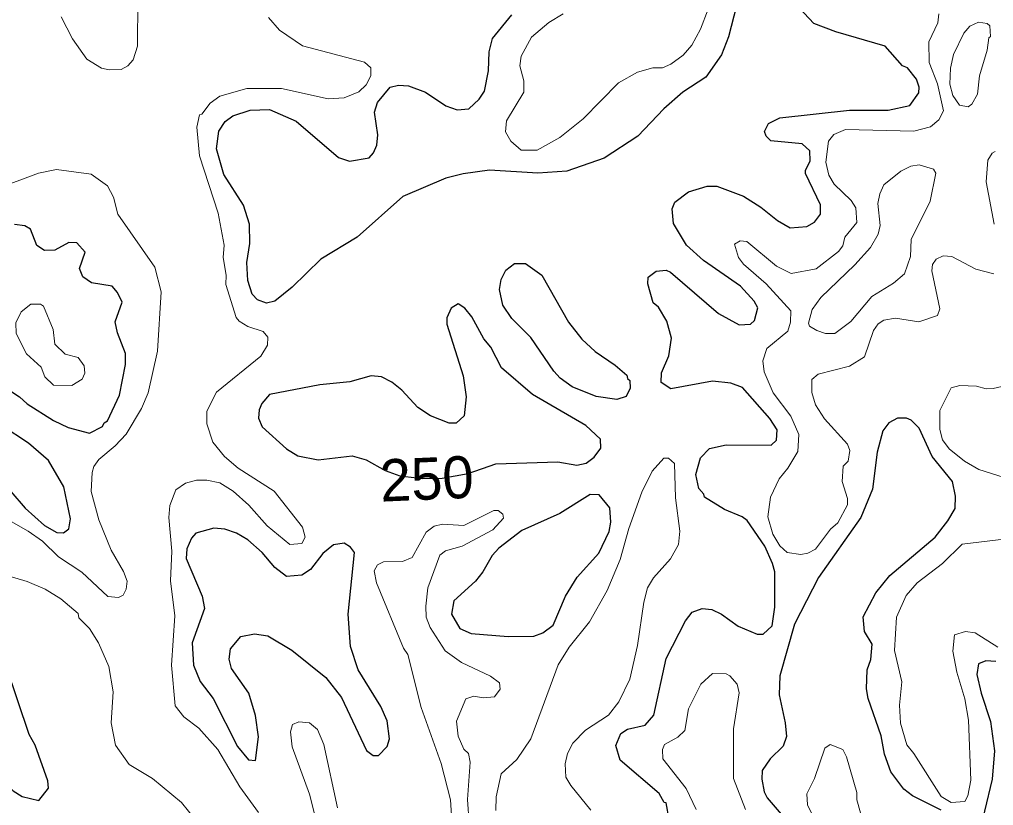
# Model space of a CAD drawing. Extents: x 763.2 to 816.8, y 7896.5 to 7952.7.
# Drawn here: x 796.187 to 799.896, y 7898.359 to 7901.353 of the extents above; entities that cross this region are included whole.
import ezdxf
from ezdxf.enums import TextEntityAlignment as Align

# ---------------------------------------------------------------- set-up
doc = ezdxf.new("R2010")
doc.units = 0
doc.header["$LTSCALE"] = 0.064
doc.layers.add('1', color=7, linetype='Continuous', lineweight=25)
doc.layers.add('2', color=7, linetype='Continuous', lineweight=13)
doc.layers.add('61', color=7, linetype='Continuous')

msp = doc.modelspace()

# ---------------------------------------------------------------- linework, layer by layer
at = {"layer": '1'}
for points in [[(798.9356, 7901.4802), (798.8867, 7901.2872), (798.8598, 7901.2183), (798.8003, 7901.1335), (798.7121, 7901.0766), (798.6398, 7901.0122), (798.5406, 7900.9081), (798.4128, 7900.8252), (798.2706, 7900.7746), (798.1604, 7900.768), (797.9763, 7900.7788), (797.8761, 7900.7646), (797.8104, 7900.7482), (797.6462, 7900.679), (797.4725, 7900.5235), (797.3341, 7900.4397), (797.2248, 7900.3328), (797.1585, 7900.2804), (797.1267, 7900.272), (797.093, 7900.2846), (797.0732, 7900.3064), (797.0558, 7900.3585), (797.0529, 7900.427), (797.0643, 7900.5), (797.0624, 7900.573), (797.0392, 7900.6453), (796.9645, 7900.7624), (796.937, 7900.8602), (796.9453, 7900.9277), (796.9696, 7900.964), (796.9986, 7900.9863), (797.0651, 7901.0079), (797.1383, 7901.0106), (797.24, 7900.9657), (797.4013, 7900.8272), (797.443, 7900.8139), (797.5176, 7900.8259), (797.535, 7900.8451), (797.5474, 7900.8738), (797.5506, 7900.9142), (797.5378, 7901.0005), (797.5497, 7901.0363), (797.5986, 7901.0947), (797.6297, 7901.1031), (797.6675, 7901.1002), (797.7332, 7901.076), (797.8105, 7901.0237), (797.8532, 7901.0091), (797.8981, 7901.0133), (797.9366, 7901.05), (797.9576, 7901.0794), (797.9731, 7901.1574), (797.9748, 7901.2297), (797.9877, 7901.2809), (798.0619, 7901.3707)], [(798.7341, 7900.6971), (798.8056, 7900.7184), (798.8425, 7900.7185), (798.9437, 7900.6795), (799.0101, 7900.638), (799.0726, 7900.5872), (799.1215, 7900.5596), (799.185, 7900.5646), (799.2138, 7900.5807), (799.2369, 7900.6119), (799.2368, 7900.6471), (799.1797, 7900.7663), (799.1799, 7900.7784), (799.1974, 7900.814), (799.1959, 7900.8521), (799.1671, 7900.8796), (799.0481, 7900.8914), (799.0297, 7900.9084), (799.0237, 7900.9259), (799.0382, 7900.9567), (799.0817, 7900.9779), (799.347, 7901.0077), (799.4941, 7901.008), (799.5774, 7901.0258), (799.6107, 7901.0737), (799.613, 7901.0948), (799.6027, 7901.1259), (799.5675, 7901.1683), (799.5495, 7901.1767), (799.4829, 7901.2514), (799.2954, 7901.3056), (799.2118, 7901.3371), (799.1552, 7901.3969)], [(798.7914, 7900.4348), (798.7264, 7900.4929), (798.6767, 7900.5756), (798.6717, 7900.6323), (798.6817, 7900.6577), (798.7341, 7900.6971)], [(796.5221, 7899.8237), (796.568, 7899.9223), (796.5908, 7900.0392), (796.5905, 7900.0805), (796.5597, 7900.159), (796.5503, 7900.2013), (796.5774, 7900.2765), (796.5594, 7900.3136), (796.5392, 7900.3373), (796.4604, 7900.3505), (796.4272, 7900.3732), (796.4154, 7900.4042), (796.4363, 7900.4665), (796.4055, 7900.5018), (796.3741, 7900.5031), (796.3214, 7900.474), (796.2821, 7900.4725), (796.2523, 7900.4927), (796.2286, 7900.5545), (796.207, 7900.567), (796.1678, 7900.5721)], [(798.6599, 7898.3051), (798.6489, 7898.3687), (798.6418, 7898.371), (798.6222, 7898.4045), (798.4738, 7898.5311), (798.458, 7898.5877), (798.4766, 7898.6335), (798.5024, 7898.6495), (798.5695, 7898.6647), (798.6026, 7898.7031), (798.6486, 7898.919), (798.7223, 7899.063), (798.7485, 7899.096), (798.7866, 7899.1094), (798.8235, 7899.1059), (798.8604, 7899.0874), (798.923, 7899.0423), (798.9954, 7899.0116), (799.0185, 7899.0111), (799.0528, 7899.0432), (799.0626, 7899.1146), (799.0625, 7899.2484), (799.0542, 7899.2813), (799.0245, 7899.347), (798.958, 7899.4442), (798.9387, 7899.4583), (798.8707, 7899.4869), (798.7951, 7899.5339), (798.7929, 7899.545), (798.7735, 7899.5666), (798.762, 7899.6202), (798.7799, 7899.6827), (798.8147, 7899.7192), (798.8771, 7899.7326), (799.0488, 7899.7309), (799.0698, 7899.7505), (799.0722, 7899.7898), (799.0441, 7899.8335), (798.9394, 7899.9518), (798.8954, 7899.9681), (798.8254, 7899.9757), (798.6673, 7899.9463), (798.6301, 7899.9698), (798.6307, 7900.0069), (798.6598, 7900.072), (798.6698, 7900.1385), (798.6518, 7900.2042), (798.6199, 7900.2571), (798.5993, 7900.2742), (798.5796, 7900.3462), (798.5805, 7900.371), (798.6112, 7900.394), (798.6486, 7900.3979), (798.6661, 7900.3908), (798.8488, 7900.2335), (798.9273, 7900.1896), (798.9701, 7900.1928), (798.9858, 7900.2064), (798.9984, 7900.2552), (798.9846, 7900.2795), (798.9327, 7900.3372), (798.7914, 7900.4348)], [(796.1226, 7899.958), (796.1869, 7899.9159), (796.2152, 7899.8895), (796.3156, 7899.8259)], [(799.6957, 7898.3411), (799.5877, 7898.3961), (799.5539, 7898.4216), (799.5041, 7898.4869), (799.48, 7898.555), (799.4684, 7898.6239), (799.418, 7898.7671), (799.4113, 7898.8033), (799.4144, 7898.8756), (799.4281, 7898.9156), (799.4341, 7898.9733), (799.4045, 7899.0217), (799.3988, 7899.078), (799.4473, 7899.1688), (799.5004, 7899.2348), (799.6739, 7899.3809), (799.7222, 7899.4434), (799.7495, 7899.4902), (799.7512, 7899.5378), (799.7395, 7899.5928), (799.6623, 7899.6889), (799.6119, 7899.7959), (799.5816, 7899.8272), (799.5648, 7899.8343), (799.5295, 7899.8343), (799.4972, 7899.8167), (799.4736, 7899.7863), (799.4524, 7899.7053), (799.4342, 7899.5641), (799.3906, 7899.4565), (799.2288, 7899.2277), (799.1381, 7899.0498), (799.0825, 7898.8526), (799.0793, 7898.781), (799.102, 7898.6733), (799.1068, 7898.6217), (799.094, 7898.5847)], [(796.1532, 7899.5554), (796.2088, 7899.4919), (796.2819, 7899.4259), (796.3288, 7899.399), (796.3542, 7899.3977), (796.375, 7899.4133), (796.3805, 7899.4508), (796.3559, 7899.5725), (796.2972, 7899.6727), (796.221, 7899.7396), (796.121, 7899.8049)], [(796.3156, 7899.8259), (796.3715, 7899.7992), (796.4536, 7899.7773), (796.5024, 7899.8023), (796.5091, 7899.8161), (796.5221, 7899.8237)], [(799.9045, 7898.9071), (799.8668, 7898.9105), (799.8384, 7898.8987), (799.832, 7898.8574), (799.8485, 7898.7869), (799.8845, 7898.6784), (799.8991, 7898.5676), (799.8904, 7898.4592), (799.8319, 7898.2149)], [(795.6717, 7898.6039), (795.7728, 7898.5126), (795.8121, 7898.4935), (795.8843, 7898.4803), (795.9205, 7898.4836), (795.9929, 7898.5031), (796.0289, 7898.5015), (796.065, 7898.49), (796.1006, 7898.4691), (796.1621, 7898.4146), (796.1974, 7898.393), (796.2598, 7898.3786), (796.2966, 7898.4252), (796.2948, 7898.453), (796.2464, 7898.5887), (796.2235, 7898.6295), (796.136, 7898.89)], [(799.094, 7898.5847), (799.0452, 7898.5366), (799.0149, 7898.492), (799.0135, 7898.4589), (799.022, 7898.4106), (799.0342, 7898.3885)], [(799.0342, 7898.3885), (799.1096, 7898.2995)]]:
    msp.add_lwpolyline(points, dxfattribs=at)
for points in [[(798.2917, 7899.9533), (798.2454, 7899.9864), (798.2208, 7900.0139), (798.1342, 7900.1417), (798.0608, 7900.2135), (798.0274, 7900.2643), (798.0146, 7900.325), (798.0209, 7900.362), (798.0391, 7900.398), (798.0718, 7900.4241), (798.1132, 7900.424), (798.175, 7900.3797), (798.2776, 7900.2003), (798.3277, 7900.1347), (798.3784, 7900.0881), (798.4552, 7900.036), (798.4995, 7899.9979), (798.5013, 7899.9854), (798.5105, 7899.9783), (798.5119, 7899.9488), (798.4967, 7899.9171), (798.4607, 7899.9052), (798.3823, 7899.9167)], [(798.14, 7899.9246), (798.0216, 7900.0265), (797.9816, 7900.1049), (797.9551, 7900.1369), (797.909, 7900.2206), (797.8826, 7900.2534), (797.8564, 7900.2693), (797.8299, 7900.2528), (797.8137, 7900.2169), (797.814, 7900.193), (797.8757, 7899.9956), (797.8875, 7899.9158), (797.8794, 7899.8435), (797.8488, 7899.8155), (797.8229, 7899.815), (797.7513, 7899.8427), (797.7031, 7899.8746), (797.6426, 7899.9414), (797.6048, 7899.9714), (797.5646, 7899.9918), (797.5253, 7899.9954), (797.445, 7899.9725), (797.3298, 7899.9608), (797.1383, 7899.9245), (797.11, 7899.8904), (797.099, 7899.8656), (797.0973, 7899.8345), (797.1107, 7899.8016), (797.203, 7899.7173), (797.2459, 7899.6913), (797.324, 7899.6751), (797.4528, 7899.6912), (797.5073, 7899.6752), (797.5788, 7899.6348), (797.6355, 7899.6151), (797.721, 7899.6044), (797.7957, 7899.6063), (797.895, 7899.624), (798.0003, 7899.6604), (798.237, 7899.6684), (798.3092, 7899.6553), (798.3448, 7899.6631), (798.3749, 7899.6856), (798.4001, 7899.7197), (798.3984, 7899.755), (798.3435, 7899.8059)], [(798.2658, 7899.1562), (798.3105, 7899.2286), (798.3925, 7899.3207), (798.4317, 7899.403), (798.4381, 7899.4384), (798.4344, 7899.4931), (798.3944, 7899.5429), (798.3594, 7899.5433), (798.2436, 7899.4709), (798.0991, 7899.4067), (798.0115, 7899.3386), (797.9863, 7899.3118), (797.9504, 7899.2484), (797.9229, 7899.2138), (797.8405, 7899.139), (797.8321, 7899.0877), (797.8639, 7899.0334), (797.9065, 7899.0144), (798.0471, 7899.0029), (798.145, 7899.0044), (798.18, 7899.0162), (798.2182, 7899.0463)], [(797.0811, 7899.0126), (797.1323, 7899.0056), (797.2236, 7898.9509), (797.3535, 7898.8467), (797.4131, 7898.7705), (797.5078, 7898.568), (797.5328, 7898.5495), (797.5539, 7898.5495), (797.5867, 7898.5838), (797.5952, 7898.6124), (797.5868, 7898.6815), (797.563, 7898.7366), (797.4757, 7898.8757), (797.4473, 7898.965), (797.4385, 7899.0876), (797.4618, 7899.3233), (797.4471, 7899.3429), (797.4235, 7899.3577), (797.3819, 7899.3521), (797.3412, 7899.3189), (797.2945, 7899.2582), (797.2614, 7899.2365), (797.2038, 7899.2313), (797.159, 7899.2652), (797.1113, 7899.3223), (797.0561, 7899.3711), (797.0124, 7899.3969), (796.969, 7899.4119), (796.927, 7899.4152), (796.8584, 7899.3967), (796.841, 7899.3774), (796.824, 7899.3365), (796.8212, 7899.2995), (796.8816, 7899.1565), (796.8914, 7899.1091), (796.8443, 7898.979), (796.849, 7898.8936), (796.874, 7898.8319), (796.9242, 7898.7668), (797.0165, 7898.5837), (797.059, 7898.5335), (797.0853, 7898.5302), (797.0969, 7898.62), (797.0857, 7898.7021), (797.0596, 7898.7868), (796.9933, 7898.8814), (796.9856, 7898.9158), (796.9899, 7898.9552), (797.03, 7899.0026)]]:
    msp.add_lwpolyline(points, close=True, dxfattribs=at)
at = {"layer": '2'}
for points in [[(796.6369, 7901.4269), (796.6356, 7901.2508), (796.6189, 7901.1989), (796.5997, 7901.1761), (796.5739, 7901.1619), (796.5275, 7901.1608), (796.4984, 7901.1676), (796.4427, 7901.2023), (796.3888, 7901.279), (796.3457, 7901.3626)], [(798.4675, 7901.1121), (798.5402, 7901.1524), (798.5987, 7901.1687), (798.6354, 7901.1691), (798.6671, 7901.1831), (798.7133, 7901.2173), (798.7464, 7901.2556), (798.7802, 7901.3159), (798.8089, 7901.3918)], [(797.1053, 7900.0711), (797.1315, 7900.113), (797.1317, 7900.1427), (797.1145, 7900.164), (797.0565, 7900.1835), (797.0229, 7900.2034), (797.0111, 7900.2173), (796.9723, 7900.3429), (796.9737, 7900.3791), (796.9626, 7900.4462), (796.9657, 7900.4937), (796.9426, 7900.6151), (796.8721, 7900.8342), (796.8622, 7900.943), (796.8719, 7900.9901), (796.8806, 7900.9926), (796.9121, 7901.0345), (796.9498, 7901.0607), (797.0526, 7901.09), (797.1846, 7901.0902), (797.362, 7901.0509), (797.4234, 7901.0541), (797.4787, 7901.0778), (797.5067, 7901.1037), (797.5242, 7901.1378), (797.5244, 7901.1692), (797.5008, 7901.1902), (797.2642, 7901.2531), (797.1772, 7901.3126), (797.1344, 7901.3609)], [(798.2574, 7901.3743), (798.2017, 7901.3413), (798.1359, 7901.2856), (798.0975, 7901.2134), (798.0915, 7901.1768)], [(799.6872, 7901.3746), (799.6838, 7901.3405), (799.6495, 7901.2684), (799.651, 7901.1893), (799.6822, 7901.1081), (799.705, 7901.0053), (799.6875, 7900.9705), (799.655, 7900.9443), (799.5919, 7900.9274), (799.3323, 7900.9338), (799.2876, 7900.9148), (799.2671, 7900.8891), (799.2567, 7900.809), (799.2687, 7900.7594), (799.2888, 7900.7257), (799.353, 7900.6632), (799.3719, 7900.6356), (799.3748, 7900.5797), (799.3296, 7900.5236), (799.3222, 7900.4909), (799.3055, 7900.4686)], [(798.0915, 7901.1768), (798.1076, 7901.1193), (798.1074, 7901.0766), (798.0407, 7900.9668), (798.0372, 7900.925), (798.0576, 7900.8892)], [(798.0576, 7900.8892), (798.0975, 7900.8558), (798.1581, 7900.8558), (798.2447, 7900.9035), (798.3325, 7900.9746), (798.4675, 7901.1121)], [(799.8976, 7900.573), (799.8681, 7900.7342), (799.8741, 7900.8165), (799.8903, 7900.8434), (799.9021, 7900.8502)], [(796.0919, 7900.7058), (796.2584, 7900.7677), (796.328, 7900.781), (796.4599, 7900.7641), (796.5218, 7900.7194), (796.5451, 7900.6768), (796.5607, 7900.6109), (796.7019, 7900.4094), (796.7256, 7900.3153), (796.7126, 7900.0893), (796.6762, 7899.9308), (796.6514, 7899.8716), (796.5925, 7899.7737), (796.5515, 7899.7293), (796.4892, 7899.6766), (796.4699, 7899.6504), (796.4629, 7899.6275), (796.4596, 7899.5546), (796.4884, 7899.4473), (796.5361, 7899.3313), (796.583, 7899.2504), (796.5968, 7899.2139), (796.5934, 7899.1828), (796.5815, 7899.1599), (796.5633, 7899.1508), (796.5226, 7899.1555), (796.4238, 7899.2476), (796.3353, 7899.3065), (796.2738, 7899.366), (796.219, 7899.4042), (796.0289, 7899.5123)], [(798.9313, 7900.5098), (798.9087, 7900.4977), (798.9244, 7900.4467), (798.9435, 7900.4208), (799.0297, 7900.3457), (799.1234, 7900.2428), (799.1229, 7900.1999), (799.1122, 7900.1655), (799.0322, 7900.0996), (799.0168, 7900.0523), (799.0219, 7900.0106), (799.0566, 7899.9309), (799.1238, 7899.842), (799.1547, 7899.7721), (799.1509, 7899.7078), (799.1129, 7899.6435), (799.0795, 7899.6033), (799.0462, 7899.533), (799.0365, 7899.4591), (799.0547, 7899.3925), (799.0825, 7899.348), (799.1093, 7899.3233), (799.1621, 7899.3153), (799.1883, 7899.3204), (799.2176, 7899.3358), (799.2745, 7899.4115), (799.3026, 7899.4352), (799.3402, 7899.5047), (799.3401, 7899.5286), (799.3198, 7899.5937), (799.3225, 7899.6514), (799.3419, 7899.6709), (799.3484, 7899.7111), (799.3393, 7899.7354), (799.2514, 7899.8318), (799.2177, 7899.8848), (799.2041, 7899.9315), (799.2041, 7899.9812), (799.2278, 7900.0019), (799.3468, 7900.0319), (799.4038, 7900.0675), (799.4392, 7900.168), (799.4565, 7900.1931), (799.4779, 7900.2071), (799.5229, 7900.2156), (799.6116, 7900.201), (799.6817, 7900.2255), (799.6917, 7900.2508), (799.661, 7900.3955), (799.6631, 7900.4191), (799.6771, 7900.4399), (799.7038, 7900.4521), (799.7368, 7900.4504), (799.8286, 7900.4015), (799.897, 7900.3842)], [(799.3055, 7900.4686), (799.2197, 7900.4032), (799.1249, 7900.385), (799.0686, 7900.4129), (798.9567, 7900.5077), (798.9313, 7900.5098)], [(796.9669, 7899.6887), (796.9227, 7899.743), (796.9001, 7899.8132), (796.9, 7899.8607), (796.937, 7899.9333), (797.1053, 7900.0711)], [(799.8676, 7899.9462), (799.8305, 7899.9562), (799.7668, 7899.9593), (799.7346, 7899.9498), (799.6906, 7899.8641), (799.6906, 7899.7912), (799.7018, 7899.752), (799.7267, 7899.7178), (799.7845, 7899.6705), (799.8398, 7899.6384), (799.9567, 7899.6026)], [(799.9597, 7899.9628), (799.8948, 7899.9469), (799.8676, 7899.9462)], [(797.0968, 7898.3329), (797.0257, 7898.4297), (796.9414, 7898.5717), (796.8691, 7898.6539), (796.8127, 7898.6973), (796.779, 7898.7384), (796.7652, 7898.8938), (796.7781, 7899.0808), (796.762, 7899.2149), (796.7667, 7899.328), (796.7553, 7899.4564), (796.7589, 7899.5015), (796.7825, 7899.561), (796.8186, 7899.5867), (796.8606, 7899.5976), (796.8999, 7899.5977), (796.9493, 7899.5879), (797.0002, 7899.5567), (797.06, 7899.5034), (797.1296, 7899.4239), (797.2159, 7899.3527), (797.262, 7899.357), (797.2746, 7899.3806), (797.2647, 7899.4187), (797.1565, 7899.5563), (797.0187, 7899.644), (796.9669, 7899.6887)], [(798.3624, 7898.3414), (798.2861, 7898.4345), (798.2674, 7898.4663), (798.2641, 7898.518), (798.2736, 7898.5569), (798.2936, 7898.5967), (798.3424, 7898.6457), (798.4294, 7898.7033), (798.4686, 7898.7544), (798.5103, 7898.8404), (798.54, 7898.9684), (798.5634, 7899.1334), (798.5777, 7899.1876), (798.6014, 7899.2267), (798.665, 7899.2987), (798.6961, 7899.353), (798.7011, 7899.4042), (798.6848, 7899.5305), (798.6814, 7899.6622), (798.6575, 7899.6816), (798.6397, 7899.6825), (798.5961, 7899.6323), (798.5564, 7899.5528), (798.5072, 7899.4147), (798.4741, 7899.2964), (798.4247, 7899.1781), (798.3569, 7899.0583), (798.2794, 7898.9624), (798.2375, 7898.8954), (798.1338, 7898.6128), (798.0809, 7898.5341), (798.0207, 7898.4794), (798.0018, 7898.3915), (798.001, 7898.3395)], [(797.8994, 7898.2906), (797.8926, 7898.3816), (797.9024, 7898.5246), (797.8959, 7898.5567), (797.8787, 7898.574), (797.8569, 7898.6226), (797.8513, 7898.6801), (797.8862, 7898.7658), (797.9163, 7898.776), (797.9516, 7898.7695), (797.9954, 7898.7734), (798.0172, 7898.8025), (798.0142, 7898.826), (797.9796, 7898.8517), (797.8702, 7898.904), (797.8072, 7898.9487), (797.75, 7899.0368), (797.7352, 7899.0762), (797.7333, 7899.1186), (797.7413, 7899.1879), (797.7871, 7899.3129), (797.8092, 7899.3291), (797.8723, 7899.3462), (797.9885, 7899.4091), (798.0302, 7899.4535), (798.0271, 7899.4683), (798.009, 7899.4821), (797.993, 7899.4825), (797.8788, 7899.4252), (797.7973, 7899.4301), (797.766, 7899.4226), (797.7349, 7899.4004), (797.6816, 7899.3039), (797.6451, 7899.2879), (797.5733, 7899.287), (797.5497, 7899.2752), (797.5377, 7899.253), (797.5458, 7899.2074), (797.6494, 7898.9588), (797.6658, 7898.9346), (797.716, 7898.7319), (797.7919, 7898.5194), (797.8283, 7898.3807), (797.8334, 7898.3012)], [(799.9987, 7899.381), (799.7765, 7899.355), (799.7014, 7899.2802), (799.6051, 7899.2066), (799.5629, 7899.1592), (799.5263, 7899.0768), (799.518, 7898.9499), (799.5459, 7898.8297), (799.5377, 7898.7408), (799.5411, 7898.6727), (799.5657, 7898.5904), (799.5926, 7898.5564), (799.6964, 7898.3938), (799.734, 7898.3698), (799.7859, 7898.3741), (799.7983, 7898.3952), (799.8088, 7898.4549), (799.8008, 7898.6843), (799.7863, 7898.7657), (799.7563, 7898.8665), (799.7401, 7898.9473), (799.7467, 7899.009), (799.7891, 7899.0223), (799.8263, 7899.0166), (799.9114, 7898.9616)], [(796.1218, 7899.2405), (796.2157, 7899.2118), (796.284, 7899.1827), (796.3445, 7899.1458), (796.4094, 7899.0904), (796.4124, 7899.0734), (796.4526, 7899.0328), (796.4872, 7898.9792), (796.5271, 7898.8887), (796.543, 7898.7923), (796.5352, 7898.6742)], [(798.9509, 7898.3431), (798.9052, 7898.4616), (798.9051, 7898.651), (798.9276, 7898.7875), (798.9197, 7898.8213), (798.8912, 7898.8535), (798.8772, 7898.8599), (798.8257, 7898.8617), (798.7813, 7898.8214), (798.7342, 7898.7271), (798.7203, 7898.6443), (798.6941, 7898.6197), (798.643, 7898.5907), (798.6355, 7898.5724), (798.6358, 7898.5366), (798.725, 7898.424), (798.7637, 7898.3432)], [(796.5352, 7898.6742), (796.5523, 7898.589), (796.6046, 7898.5152), (796.6929, 7898.4621), (796.8029, 7898.37), (796.8572, 7898.3044)], [(797.3973, 7898.3503), (797.345, 7898.5909), (797.3208, 7898.6486), (797.291, 7898.6739), (797.2506, 7898.6774), (797.2261, 7898.6674), (797.219, 7898.6396), (797.2247, 7898.5828), (797.2913, 7898.4024), (797.3304, 7898.2459)], [(799.3895, 7898.3314), (799.3754, 7898.3805), (799.3748, 7898.4088), (799.3354, 7898.5443), (799.3216, 7898.5725), (799.2732, 7898.5917), (799.2528, 7898.5775), (799.2138, 7898.4623), (799.1845, 7898.4031), (799.1877, 7898.3612), (799.217, 7898.3018)]]:
    msp.add_lwpolyline(points, dxfattribs=at)
for points in [[(799.7315, 7901.1679), (799.7433, 7901.2198), (799.782, 7901.3006), (799.8053, 7901.3279), (799.8389, 7901.3432), (799.8712, 7901.3378), (799.882, 7901.3288), (799.8844, 7901.2883), (799.878, 7901.2833), (799.8711, 7901.2357), (799.842, 7901.1384), (799.8351, 7901.0683), (799.8134, 7901.0305), (799.7985, 7901.0197), (799.7664, 7901.026), (799.7401, 7901.063), (799.7287, 7901.1067)], [(799.5424, 7900.7748), (799.5804, 7900.7941), (799.613, 7900.799), (799.6675, 7900.7827), (799.6756, 7900.7676), (799.6541, 7900.6605), (799.5826, 7900.5145), (799.5792, 7900.4496), (799.556, 7900.3842), (799.5147, 7900.3489), (799.4317, 7900.2974), (799.3526, 7900.2031), (799.2914, 7900.157), (799.2552, 7900.1569), (799.2223, 7900.168), (799.1955, 7900.1851), (799.1913, 7900.1965), (799.2052, 7900.2489), (799.2374, 7900.2934), (799.3674, 7900.4185), (799.4267, 7900.4849), (799.4565, 7900.535), (799.4635, 7900.5684), (799.4556, 7900.6526), (799.4621, 7900.6884), (799.4777, 7900.7226)], [(796.3212, 7900.1168), (796.3146, 7900.1717), (796.2784, 7900.2614), (796.2661, 7900.2683), (796.2296, 7900.2681), (796.193, 7900.2399), (796.1732, 7900.1971), (796.1734, 7900.1565), (796.2127, 7900.0795), (796.2686, 7900.0281), (796.2826, 7899.9912), (796.3167, 7899.9595), (796.386, 7899.9592), (796.4253, 7899.983), (796.4352, 7900.006), (796.4335, 7900.0341), (796.4096, 7900.0651), (796.361, 7900.0779)]]:
    msp.add_lwpolyline(points, close=True, dxfattribs=at)

# ---------------------------------------------------------------- texts
at = {"layer": '61'}
msp.add_text('250', height=0.16, rotation=2.513, dxfattribs=at).set_placement((797.7407, 7899.524), align=Align.CENTER)

doc.saveas('drawing.dxf')
